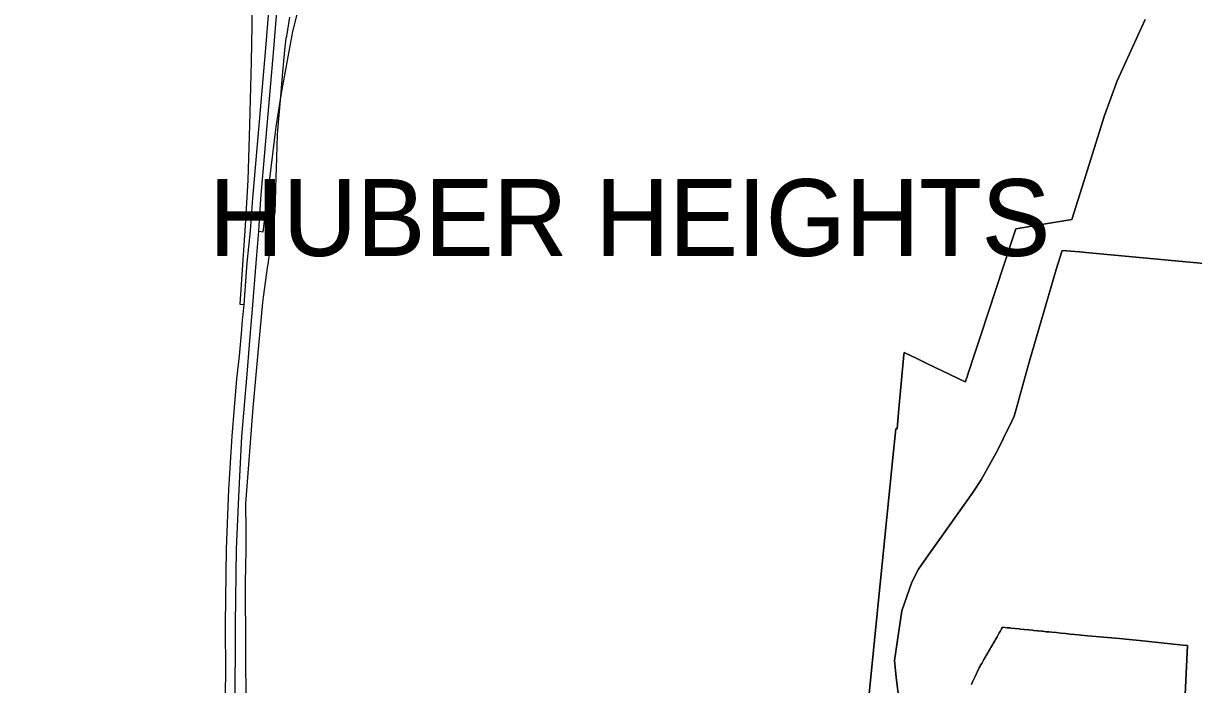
# Model space of a CAD drawing. Extents: x 0 to 34, y 0 to 22.
# Drawn here: x 5.2973 to 5.4203, y 15.6943 to 15.7638 of the extents above; entities that cross this region are included whole.
import ezdxf

# ---------------------------------------------------------------- set-up
doc = ezdxf.new("R2010")
doc.units = 0
for name, color, linetype in [('GM_X_Corporation', 7, 'Continuous'), ('GM_X_Corporation_Text', 7, 'Continuous'), ('GM_X_Interchange_Ramps', 7, 'Continuous'), ('GM_X_Interstate_Route', 7, 'Continuous')]:
    doc.layers.add(name, color=color, linetype=linetype)

msp = doc.modelspace()

# ---------------------------------------------------------------- linework, layer by layer
at = {"layer": 'GM_X_Corporation'}
for points in [[(5.32076, 15.69174), (5.32069, 15.70479), (5.32073, 15.70695), (5.32076, 15.70835), (5.32076, 15.7105), (5.32071, 15.71333), (5.32114, 15.7188), (5.32151, 15.72338), (5.32208, 15.72994), (5.3225, 15.73446), (5.32258, 15.73502), (5.32303, 15.73833), (5.32306, 15.73849), (5.32342, 15.74114), (5.32372, 15.7433), (5.32378, 15.7437), (5.32382, 15.74403), (5.32385, 15.74498), (5.32385, 15.74517), (5.32385, 15.7452), (5.32388, 15.74632), (5.32392, 15.74772), (5.32394, 15.74849), (5.32404, 15.75208), (5.32408, 15.75254), (5.32436, 15.75572), (5.32447, 15.75696), (5.32451, 15.75743), (5.32463, 15.75866), (5.32484, 15.76097), (5.32496, 15.76223), (5.32503, 15.76244), (5.32534, 15.76441)], [(5.41525, 15.76419), (5.41232, 15.75774), (5.41096, 15.75409), (5.40882, 15.74717), (5.40755, 15.74316), (5.40608, 15.74292), (5.40563, 15.74285), (5.4054, 15.74281), (5.40167, 15.7422), (5.40041, 15.73838), (5.39794, 15.73091), (5.39707, 15.7283), (5.39685, 15.72764), (5.39669, 15.72715), (5.39653, 15.72666), (5.39641, 15.7263), (5.39636, 15.72614), (5.39635, 15.72614), (5.39232, 15.72806), (5.39148, 15.72846), (5.39038, 15.72899), (5.39035, 15.729), (5.38992, 15.7292), (5.38991, 15.7292), (5.3899, 15.72901), (5.38934, 15.72289), (5.38919, 15.72118), (5.38903, 15.72118), (5.3888, 15.71885), (5.38669, 15.69795), (5.38613, 15.69231)], [(5.38613, 15.69231), (5.38669, 15.69795), (5.3888, 15.71885), (5.38903, 15.72118), (5.38919, 15.72118), (5.38934, 15.72289), (5.3899, 15.72901), (5.38991, 15.7292), (5.38992, 15.7292), (5.39035, 15.729), (5.39038, 15.72899), (5.39148, 15.72846), (5.39232, 15.72806), (5.39635, 15.72614), (5.39636, 15.72614), (5.39641, 15.7263), (5.39653, 15.72666), (5.39669, 15.72715), (5.39685, 15.72764), (5.39707, 15.7283), (5.39794, 15.73091), (5.40041, 15.73838), (5.40167, 15.7422), (5.4054, 15.74281), (5.40563, 15.74285), (5.40608, 15.74292), (5.40755, 15.74316), (5.40882, 15.74717), (5.41096, 15.75409), (5.41232, 15.75774), (5.41525, 15.76419)], [(5.42141, 15.73856), (5.40902, 15.7397), (5.40837, 15.73976), (5.40836, 15.73976), (5.40652, 15.73993), (5.40588, 15.73791), (5.40306, 15.72818), (5.40201, 15.72441), (5.40193, 15.72413), (5.40155, 15.72276), (5.40148, 15.72252), (5.40105, 15.72162), (5.40089, 15.72128), (5.39977, 15.71897), (5.39803, 15.71584), (5.39713, 15.71451), (5.39387, 15.70992), (5.39248, 15.70795), (5.39144, 15.70644), (5.39073, 15.70509), (5.38967, 15.70206), (5.3889, 15.69687), (5.38907, 15.69508), (5.38944, 15.69233)], [(5.38944, 15.69235), (5.38907, 15.69508), (5.3889, 15.69687), (5.38967, 15.70206), (5.39073, 15.70509), (5.39144, 15.70644), (5.39248, 15.70795), (5.39387, 15.70992), (5.39713, 15.71451), (5.39803, 15.71584), (5.39977, 15.71897), (5.40089, 15.72128), (5.40105, 15.72162), (5.40148, 15.72252), (5.40155, 15.72276), (5.40193, 15.72413), (5.40201, 15.72441), (5.40306, 15.72818), (5.40588, 15.73791), (5.40652, 15.73993), (5.40836, 15.73976), (5.40837, 15.73976), (5.40902, 15.7397), (5.42141, 15.73856)], [(5.39699, 15.69432), (5.39712, 15.69461), (5.39719, 15.69476), (5.39733, 15.69505), (5.39739, 15.69519), (5.39753, 15.69549), (5.3976, 15.69563), (5.39774, 15.69593), (5.3978, 15.69607), (5.39786, 15.69619), (5.39796, 15.69636), (5.39807, 15.69655), (5.39823, 15.69683), (5.39831, 15.69696), (5.39847, 15.69725), (5.39855, 15.69738), (5.39871, 15.69766), (5.39879, 15.6978), (5.39895, 15.69808), (5.39903, 15.69822), (5.39919, 15.6985), (5.39927, 15.69863), (5.39944, 15.69892), (5.39951, 15.69905), (5.39968, 15.69933), (5.39976, 15.69947), (5.39992, 15.69975), (5.4, 15.69989), (5.40016, 15.70017), (5.40026, 15.70034), (5.40075, 15.70029), (5.40103, 15.70027), (5.40112, 15.70026), (5.40156, 15.70022), (5.4016, 15.70021), (5.40203, 15.70017), (5.40208, 15.70016), (5.40251, 15.70012), (5.40256, 15.70012), (5.40298, 15.70007), (5.40304, 15.70007), (5.40345, 15.70003), (5.40352, 15.70002), (5.40392, 15.69998), (5.404, 15.69997), (5.40439, 15.69993), (5.40448, 15.69992), (5.40486, 15.69988), (5.40496, 15.69987), (5.40512, 15.69986), (5.40544, 15.69983), (5.40592, 15.69978), (5.4064, 15.69973), (5.40688, 15.69968), (5.40736, 15.69963), (5.40784, 15.69958), (5.40825, 15.69954), (5.40853, 15.69951), (5.40924, 15.69945), (5.41212, 15.6992), (5.41257, 15.69915), (5.41358, 15.69905), (5.41464, 15.69894), (5.41888, 15.6985), (5.41958, 15.69843), (5.4197, 15.69842), (5.4192, 15.68816)], [(5.4192, 15.68816), (5.4197, 15.69842), (5.41958, 15.69843), (5.41888, 15.6985), (5.41464, 15.69894), (5.41358, 15.69905), (5.41257, 15.69915), (5.41212, 15.6992), (5.40924, 15.69945), (5.40853, 15.69951), (5.40825, 15.69954), (5.40784, 15.69958), (5.40736, 15.69963), (5.40688, 15.69968), (5.4064, 15.69973), (5.40592, 15.69978), (5.40544, 15.69983), (5.40512, 15.69986), (5.40496, 15.69987), (5.40486, 15.69988), (5.40448, 15.69992), (5.40439, 15.69993), (5.404, 15.69997), (5.40392, 15.69998), (5.40352, 15.70002), (5.40345, 15.70003), (5.40304, 15.70007), (5.40298, 15.70007), (5.40256, 15.70012), (5.40251, 15.70012), (5.40208, 15.70016), (5.40203, 15.70017), (5.4016, 15.70021), (5.40156, 15.70022), (5.40112, 15.70026), (5.40103, 15.70027), (5.40075, 15.70029), (5.40026, 15.70034), (5.40016, 15.70017), (5.4, 15.69989), (5.39992, 15.69975), (5.39976, 15.69947), (5.39968, 15.69933), (5.39951, 15.69905), (5.39944, 15.69892), (5.39927, 15.69863), (5.39919, 15.6985), (5.39903, 15.69822), (5.39895, 15.69808), (5.39879, 15.6978), (5.39871, 15.69766), (5.39855, 15.69738), (5.39847, 15.69725), (5.39831, 15.69696), (5.39823, 15.69683), (5.39807, 15.69655), (5.39796, 15.69636), (5.39786, 15.69619), (5.3978, 15.69607), (5.39774, 15.69593), (5.3976, 15.69563), (5.39753, 15.69549), (5.39739, 15.69519), (5.39733, 15.69505), (5.39719, 15.69476), (5.39712, 15.69461), (5.39699, 15.69432)]]:
    msp.add_lwpolyline(points, dxfattribs=at)
at = {"layer": 'GM_X_Interchange_Ramps'}
for points in [[(5.29465, 15.78511), (5.29903, 15.7848), (5.30195, 15.78453), (5.30404, 15.78428), (5.30612, 15.78388), (5.30819, 15.78326), (5.31013, 15.78248), (5.312, 15.78146), (5.31374, 15.78025), (5.31532, 15.77884), (5.31674, 15.77731), (5.31804, 15.77559), (5.31911, 15.7738), (5.31999, 15.77186), (5.32068, 15.76983), (5.32111, 15.76776), (5.32132, 15.76568), (5.32137, 15.76355), (5.32127, 15.75974), (5.3211, 15.75307), (5.32093, 15.74729), (5.32066, 15.74255), (5.3201, 15.73427), (5.32055, 15.73426)], [(5.32437, 15.75579), (5.32453, 15.75681), (5.32567, 15.76293), (5.32615, 15.76486), (5.32659, 15.76637), (5.32709, 15.7679), (5.32749, 15.76897)], [(5.3221, 15.74193), (5.32255, 15.74188), (5.32317, 15.7469), (5.32392, 15.7529), (5.32437, 15.75579)]]:
    msp.add_lwpolyline(points, dxfattribs=at)
at = {"layer": 'GM_X_Interstate_Route'}
for points in [[(5.32112, 15.73002), (5.32122, 15.7313), (5.3213, 15.73214), (5.32137, 15.73292), (5.32148, 15.7342), (5.32182, 15.73859), (5.3221, 15.74193), (5.32231, 15.74536), (5.32285, 15.75182), (5.32362, 15.76069), (5.32401, 15.76542), (5.32469, 15.77348), (5.32498, 15.77672), (5.3251, 15.77801), (5.32534, 15.78113), (5.32557, 15.78375), (5.32576, 15.78611), (5.32578, 15.78637), (5.32585, 15.78714)], [(5.31856, 15.69207), (5.31861, 15.69538), (5.31859, 15.7007), (5.31869, 15.70857), (5.31893, 15.71482), (5.31929, 15.72042), (5.31979, 15.72643), (5.32005, 15.72885), (5.3203, 15.73157), (5.32039, 15.73263), (5.32044, 15.73318), (5.32055, 15.73426), (5.32088, 15.73861), (5.32121, 15.74199), (5.32148, 15.7454), (5.32202, 15.75187), (5.32279, 15.76073), (5.32318, 15.76547)], [(5.31965, 15.7001), (5.31965, 15.7007), (5.31975, 15.70854), (5.32002, 15.7148), (5.32032, 15.72037), (5.32087, 15.72693), (5.32112, 15.73002)], [(5.31962, 15.68302), (5.31963, 15.68369), (5.31961, 15.69218), (5.31965, 15.7001)]]:
    msp.add_lwpolyline(points, dxfattribs=at)

# ---------------------------------------------------------------- texts
at = {"layer": 'GM_X_Corporation_Text'}
for p in [(5.31684, 15.73934), (5.31691, 15.73938)]:
    msp.add_text('HUBER HEIGHTS', height=0.008037, rotation=0, dxfattribs=at).set_placement(p)

doc.saveas('drawing.dxf')
